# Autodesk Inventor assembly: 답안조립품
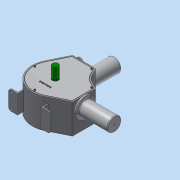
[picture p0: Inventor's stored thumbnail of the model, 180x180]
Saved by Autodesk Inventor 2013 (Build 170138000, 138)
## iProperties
Created: 2017-05
Part Number: 답안조립품
Document SubType Name: Assembly
Designer: dgall
Author: dgall
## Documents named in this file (13)
- C:\Users\dgall\Desktop\370507V1012\답안조립품.iam
- C:\Users\dgall\Desktop\370507V1012\본체.ipt
- C:\Users\dgall\Desktop\370507V1012\앞커버.ipt
- C:\Users\dgall\Desktop\370507V1012\축.ipt
- C:\Users\dgall\Desktop\370507V1012\베어링 20 x 37 x 9.ipt
- C:\Users\dgall\Desktop\370507V1012\커넥팅로드.ipt
- C:\Users\dgall\Desktop\370507V1012\커넥팅로드 캡.ipt
- C:\Users\dgall\Desktop\370507V1012\측정게이지.ipt
- C:\Users\dgall\Desktop\370507V1012\실린더.ipt
- C:\Users\dgall\Desktop\370507V1012\피스톤.ipt
- C:\Users\dgall\Desktop\370507V1012\피스톤 핀.ipt
- C:\Users\dgall\Desktop\370507V1012\볼트 M3 x 12.ipt
- C:\Users\dgall\Desktop\370507V1012\너트 M3.ipt
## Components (4 placed, 2 different names)
1. 피스톤:1
2. 피스톤 핀:1
3. 피스톤:2
4. 피스톤 핀:2
